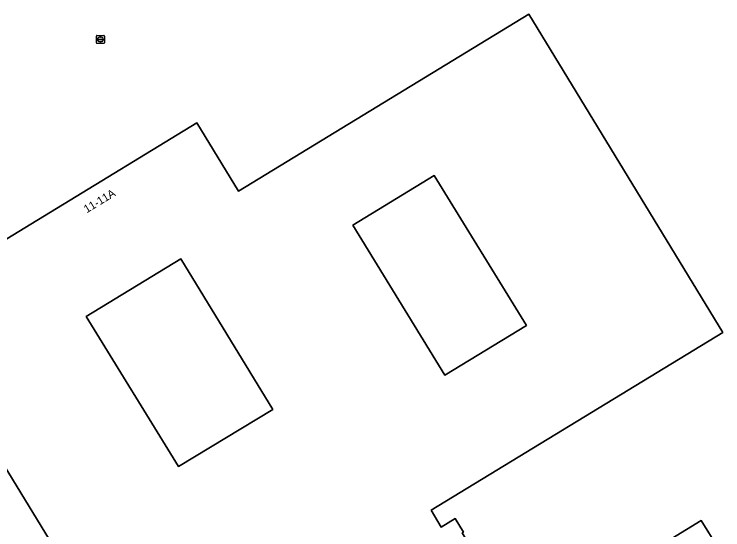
# Model space of a CAD drawing. Extents: x 158455 to 159797, y 387218 to 388672.
# Drawn here: x 158893.3 to 158981.9, y 387353.5 to 387418 of the extents above; entities that cross this region are included whole.
import ezdxf

# ---------------------------------------------------------------- set-up
doc = ezdxf.new("R2010")
doc.units = 0
for name, color, linetype in [('IMGEO_Erf', 7, 'Continuous'), ('IMGEO_Kolk', 7, 'Continuous'), ('IMGEO_Pand', 7, 'Continuous'), ('IMGEO_Pand_nummerreeks', 7, 'Continuous')]:
    doc.layers.add(name, color=color, linetype=linetype)

msp = doc.modelspace()

# ---------------------------------------------------------------- linework, layer by layer
at = {"layer": 'IMGEO_Erf'}
for points in [[(158879.514, 387382.047), (158916.143, 387404.386), (158921.348, 387395.853), (158957.615, 387417.96), (158981.859, 387378.192), (158945.397, 387355.962), (158946.676, 387353.856), (158948.411, 387354.921), (158949.448, 387353.208), (158949.303, 387353.117), (158960.891, 387334.055), (158950.276, 387327.603), (158949.505, 387328.872), (158946.453, 387327.017), (158947.291, 387325.64), (158926.4, 387312.942), (158925.637, 387314.197), (158922.636, 387312.372), (158923.447, 387311.037), (158912.817, 387304.575), (158910.22, 387308.848), (158901.099, 387323.853), (158911.261, 387330.04)], [(158945.796, 387397.78), (158935.619, 387391.582), (158947.131, 387372.822), (158957.336, 387379.033)], [(158902.319, 387380.189), (158913.841, 387361.435), (158925.638, 387368.565), (158914.133, 387387.387)], [(158979.16, 387354.698), (158981.275, 387351.256), (158968.436, 387343.375), (158966.324, 387346.816)]]:
    msp.add_lwpolyline(points, close=True, dxfattribs=at)
at = {"layer": 'IMGEO_Kolk'}
for p, q in [((158903.583, 387414.376), (158903.583, 387415.228)), ((158903.658, 387415.302), (158904.51, 387415.302)), ((158903.842, 387414.796), (158903.842, 387414.808)), ((158904.28, 387414.759), (158903.882, 387414.759)), ((158903.885, 387414.845), (158904.283, 387414.845)), ((158904.094, 387414.522), (158904.069, 387414.522)), ((158904.071, 387415.082), (158904.096, 387415.082)), ((158904.326, 387414.808), (158904.326, 387414.796)), ((158904.584, 387415.228), (158904.584, 387414.376)), ((158904.51, 387414.302), (158903.658, 387414.302))]:
    msp.add_line(p, q, dxfattribs=at)
for points in [[(158903.583, 387414.376), (158903.583, 387415.228)], [(158903.658, 387415.302), (158904.51, 387415.302)], [(158904.584, 387415.228), (158904.584, 387414.376)], [(158904.51, 387414.302), (158903.658, 387414.302)]]:
    msp.add_lwpolyline(points, dxfattribs=at)
for centre, radius, start, end in [((158903.66, 387415.226), 0.0765, 91.55205, 178.44795), ((158903.66, 387415.226), 0.0765, 91.55205, 178.44795), ((158903.882, 387414.805), 0.0403, 85.87752, 175.75265), ((158903.879, 387414.795), 0.0366, 178.93798, 274.71019), ((158904.283, 387414.802), 0.043, 264.86636, 352.45326), ((158904.287, 387414.807), 0.0386, 1.73085, 96.63898), ((158904.508, 387415.226), 0.0765, 1.55205, 88.44795), ((158904.508, 387415.226), 0.0765, 1.55205, 88.44795), ((158903.66, 387414.378), 0.0765, 181.55205, 268.44795), ((158903.66, 387414.378), 0.0765, 181.55205, 268.44795), ((158904.508, 387414.378), 0.0765, 271.55205, 358.44795), ((158904.508, 387414.378), 0.0765, 271.55205, 358.44795)]:
    msp.add_arc(centre, radius, start, end, dxfattribs=at)
for centre, major_axis, ratio, start_param, end_param in [((158904.07, 387414.802), (-0.387, 0.002), 0.722429, 4.712389, 7.853982), ((158904.095, 387414.802), (-0.39, 0.002), 0.717154, 1.570796, 4.712389)]:
    msp.add_ellipse(centre, major_axis=major_axis, ratio=ratio, start_param=start_param, end_param=end_param, dxfattribs=at)
at = {"layer": 'IMGEO_Pand'}
for points in [[(158981.859, 387378.192), (158957.615, 387417.96), (158921.348, 387395.853), (158916.143, 387404.386), (158879.514, 387382.047), (158911.261, 387330.04), (158901.099, 387323.853), (158910.22, 387308.848), (158912.817, 387304.575), (158923.447, 387311.037), (158922.636, 387312.372), (158925.637, 387314.197), (158926.4, 387312.942), (158947.291, 387325.64), (158946.453, 387327.017), (158949.505, 387328.872), (158950.276, 387327.603), (158960.891, 387334.055), (158949.303, 387353.117), (158949.448, 387353.208), (158948.411, 387354.921), (158946.676, 387353.856), (158945.397, 387355.962)], [(158947.131, 387372.822), (158935.619, 387391.582), (158945.796, 387397.78), (158957.336, 387379.033)], [(158913.841, 387361.435), (158902.319, 387380.189), (158914.133, 387387.387), (158925.638, 387368.565)], [(158981.275, 387351.256), (158979.16, 387354.698), (158966.324, 387346.816), (158968.436, 387343.375)]]:
    msp.add_lwpolyline(points, close=True, dxfattribs=at)

# ---------------------------------------------------------------- texts
at = {"layer": 'IMGEO_Pand_nummerreeks'}
msp.add_text('11-11A', height=1, rotation=31.37517, dxfattribs=at).set_placement((158902.385, 387393.067))

doc.saveas('drawing.dxf')
